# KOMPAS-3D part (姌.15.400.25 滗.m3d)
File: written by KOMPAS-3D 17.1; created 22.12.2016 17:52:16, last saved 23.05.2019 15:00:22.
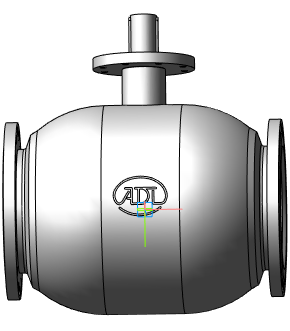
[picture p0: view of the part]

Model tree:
1. Операция без истории:7  (labels: Сталь 20  ГОСТ 1050-88)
